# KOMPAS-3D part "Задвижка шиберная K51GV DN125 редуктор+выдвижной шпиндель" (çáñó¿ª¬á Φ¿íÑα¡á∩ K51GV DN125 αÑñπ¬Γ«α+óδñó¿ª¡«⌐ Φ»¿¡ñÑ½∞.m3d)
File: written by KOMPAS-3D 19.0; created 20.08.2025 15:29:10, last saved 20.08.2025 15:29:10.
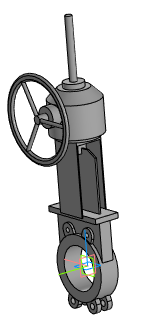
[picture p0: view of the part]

Document properties: Полное имя файла: Задвижка шиберная K51GV DN125 редуктор+выдвижной шпиндель.a3d

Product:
- Part/product: Задвижка шиберная K51GV DN125 редуктор+выдвижной шпиндель
    Масса: 34.4402

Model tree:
1. Операция без истории:1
